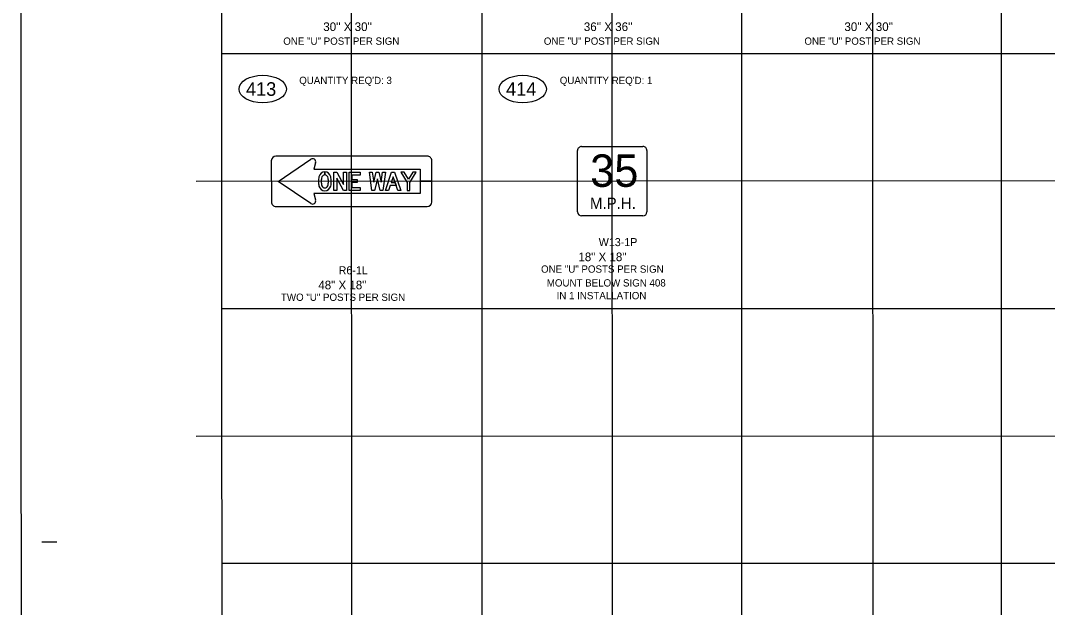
# Model space of a CAD drawing. Extents: x 1977705 to 1981198, y 827296 to 829291.
# Drawn here: x 1979337 to 1980184, y 827837 to 828321 of the extents above; entities that cross this region are included whole.
import ezdxf

# ---------------------------------------------------------------- set-up
doc = ezdxf.new("R2010")
doc.units = 0
for name, color, linetype in [('Level 3', 7, 'Continuous'), ('Level 34', 7, 'Continuous'), ('Level 43', 7, 'Continuous'), ('Level 46', 7, 'Continuous'), ('Level 5', 7, 'Continuous'), ('Level 7', 7, 'Continuous')]:
    doc.layers.add(name, color=color, linetype=linetype)

msp = doc.modelspace()

# ---------------------------------------------------------------- linework, layer by layer
at = {"layer": 'Level 3'}
msp.add_lwpolyline([(1981020.16, 828736.58), (1979336.66, 828735.68), (1979337.25, 827640.68), (1981020.75, 827641.58)], close=True, dxfattribs=at)
at = {"layer": 'Level 34'}
for p, q in [((1979610.04, 827663.85), (1979609.44, 828783.03)), ((1979824.92, 827663.96), (1979824.32, 828783.14)), ((1980039.8, 827664.08), (1980039.2, 828783.26)), ((1981002.08, 828188.92), (1979481.44, 828188.11)), ((1981002.19, 827978.73), (1979481.55, 827977.92))]:
    msp.add_line(p, q, dxfattribs=at)
at = {"layer": 'Level 43'}
for p, q in [((1979543.48, 828205.15), (1979543.5, 828171.13)), ((1979672, 828209), (1979547.26, 828208.93)), ((1979587.61, 828193.48), (1979587.61, 828195.91)), ((1979587.61, 828195.91), (1979587.61, 828193.48)), ((1979587.61, 828193.48), (1979587.61, 828195.91)), ((1979587.61, 828195.91), (1979587.61, 828193.48)), ((1979587.61, 828193.48), (1979587.61, 828193.48)), ((1979587.61, 828193.48), (1979587.61, 828193.48)), ((1979547.28, 828167.35), (1979672.02, 828167.42))]:
    msp.add_line(p, q, dxfattribs=at)
for points in [[(1979576.06, 828169.94), (1979549.16, 828188.14), (1979576.04, 828206.37)], [(1979580, 828203.51), (1979578.45, 828198.08), (1979666.34, 828198.13), (1979666.34, 828188.21), (1979675.79, 828188.22), (1979675.78, 828205.22)], [(1979675.8, 828171.21), (1979675.79, 828188.21), (1979666.34, 828188.21), (1979666.35, 828178.29), (1979578.46, 828178.24), (1979580.01, 828172.81)]]:
    msp.add_lwpolyline(points, dxfattribs=at)
for points in [[(1979595.15, 828180.61), (1979595.15, 828195.73), (1979597.56, 828195.73), (1979602.98, 828185.67), (1979602.97, 828195.73), (1979605.35, 828195.73), (1979605.36, 828180.61), (1979602.98, 828180.61), (1979597.53, 828190.73), (1979597.54, 828180.61)], [(1979595.15, 828180.61), (1979595.15, 828195.73), (1979597.56, 828195.73), (1979602.98, 828185.67), (1979602.97, 828195.73), (1979605.35, 828195.73), (1979605.36, 828180.61), (1979602.98, 828180.61), (1979597.53, 828190.73), (1979597.54, 828180.61)], [(1979595.15, 828180.61), (1979595.15, 828195.73), (1979597.56, 828195.73), (1979602.98, 828185.67), (1979602.97, 828195.73), (1979605.35, 828195.73), (1979605.36, 828180.61), (1979602.98, 828180.61), (1979597.53, 828190.73), (1979597.54, 828180.61)], [(1979616.79, 828193.32), (1979609.94, 828193.32), (1979609.94, 828189.69), (1979614.27, 828189.69), (1979614.27, 828187.27), (1979609.94, 828187.27), (1979609.95, 828183.03), (1979616.8, 828183.04), (1979616.8, 828180.62), (1979607.56, 828180.61), (1979607.55, 828195.73), (1979616.79, 828195.74)], [(1979616.79, 828193.32), (1979609.94, 828193.32), (1979609.94, 828189.69), (1979614.27, 828189.69), (1979614.27, 828187.27), (1979609.94, 828187.27), (1979609.95, 828183.03), (1979616.8, 828183.04), (1979616.8, 828180.62), (1979607.56, 828180.61), (1979607.55, 828195.73), (1979616.79, 828195.74)], [(1979616.79, 828193.32), (1979609.94, 828193.32), (1979609.94, 828189.69), (1979614.27, 828189.69), (1979614.27, 828187.27), (1979609.94, 828187.27), (1979609.95, 828183.03), (1979616.8, 828183.04), (1979616.8, 828180.62), (1979607.56, 828180.61), (1979607.55, 828195.73), (1979616.79, 828195.74)], [(1979627.89, 828187.57), (1979629.85, 828195.75), (1979632.09, 828195.75), (1979634.07, 828187.57), (1979635.19, 828195.75), (1979637.6, 828195.75), (1979635.52, 828180.63), (1979633.29, 828180.63), (1979630.97, 828190.22), (1979628.67, 828180.63), (1979626.44, 828180.63), (1979624.34, 828195.74), (1979626.75, 828195.74)], [(1979627.89, 828187.57), (1979629.85, 828195.75), (1979632.09, 828195.75), (1979634.07, 828187.57), (1979635.19, 828195.75), (1979637.6, 828195.75), (1979635.52, 828180.63), (1979633.29, 828180.63), (1979630.97, 828190.22), (1979628.67, 828180.63), (1979626.44, 828180.63), (1979624.34, 828195.74), (1979626.75, 828195.74)], [(1979627.89, 828187.57), (1979629.85, 828195.75), (1979632.09, 828195.75), (1979634.07, 828187.57), (1979635.19, 828195.75), (1979637.6, 828195.75), (1979635.52, 828180.63), (1979633.29, 828180.63), (1979630.97, 828190.22), (1979628.67, 828180.63), (1979626.44, 828180.63), (1979624.34, 828195.74), (1979626.75, 828195.74)], [(1979641.52, 828184.79), (1979640.12, 828180.64), (1979637.61, 828180.63), (1979642.66, 828195.75), (1979645.19, 828195.75), (1979650.27, 828180.64), (1979647.75, 828180.64), (1979646.35, 828184.79)], [(1979637.61, 828180.63), (1979642.66, 828195.75), (1979645.19, 828195.75), (1979650.27, 828180.64), (1979647.75, 828180.64), (1979643.93, 828192.02), (1979642.32, 828187.21), (1979645.54, 828187.21), (1979646.35, 828184.79), (1979641.52, 828184.79), (1979640.12, 828180.64)], [(1979637.61, 828180.63), (1979642.66, 828195.75), (1979645.19, 828195.75), (1979650.27, 828180.64), (1979647.75, 828180.64), (1979643.93, 828192.02), (1979642.32, 828187.21), (1979645.54, 828187.21), (1979646.35, 828184.79), (1979641.52, 828184.79), (1979640.12, 828180.64)], [(1979650.26, 828195.76), (1979655.44, 828187.26), (1979655.45, 828180.64), (1979657.83, 828180.65), (1979657.82, 828187.26), (1979662.99, 828195.76), (1979660.19, 828195.76), (1979656.63, 828189.9), (1979653.06, 828195.76)], [(1979650.26, 828195.76), (1979655.44, 828187.26), (1979655.45, 828180.64), (1979657.83, 828180.65), (1979657.82, 828187.26), (1979662.99, 828195.76), (1979660.19, 828195.76), (1979656.63, 828189.9), (1979653.06, 828195.76)], [(1979650.26, 828195.76), (1979655.44, 828187.26), (1979655.45, 828180.64), (1979657.83, 828180.65), (1979657.82, 828187.26), (1979662.99, 828195.76), (1979660.19, 828195.76), (1979656.63, 828189.9), (1979653.06, 828195.76)], [(1979642.32, 828187.21), (1979645.54, 828187.21), (1979643.93, 828192.02)]]:
    msp.add_lwpolyline(points, close=True, dxfattribs=at)
for centre, radius, start, end in [((1979547.26, 828205.15), 3.78, 90.03168, 180.03081), ((1979577.5, 828204.22), 2.6, 344.07596, 124.148), ((1979672, 828205.22), 3.78, 0.03081, 90.03168), ((1979547.28, 828171.13), 3.78, 180.03081, 270.03168), ((1979577.52, 828172.09), 2.6, 235.91363, 15.98567), ((1979672.02, 828171.2), 3.78, 270.03168, 0.03081)]:
    msp.add_arc(centre, radius, start, end, dxfattribs=at)
for centre, major_axis, start_param, end_param in [((1979587.64, 828190.8), (0, 5.12), 0.007008, 1.34227), ((1979587.64, 828190.8), (0, 5.12), 0.007008, 1.34227), ((1979587.64, 828190.8), (0, 5.12), 0.007008, 1.34227), ((1979587.57, 828190.8), (0, 5.12), 4.940915, 6.276178), ((1979587.57, 828190.8), (0, 5.12), 4.940915, 6.27603), ((1979587.57, 828190.8), (0, 5.12), 4.940915, 6.27603), ((1979597.57, 828188.22), (-0.01, 15.52), 1.327472, 1.575821), ((1979597.57, 828188.22), (-0.01, 15.52), 1.327472, 1.575821), ((1979597.57, 828188.22), (-0.01, 15.52), 1.327472, 1.575821), ((1979597.57, 828188.07), (-0.01, 15.52), 1.565772, 1.814121), ((1979597.57, 828188.07), (-0.01, 15.52), 1.565772, 1.814121), ((1979597.57, 828188.07), (-0.01, 15.52), 1.565772, 1.814121), ((1979595.9, 828188.42), (-0.01, 11.38), 1.267043, 1.594924), ((1979595.9, 828188.42), (-0.01, 11.38), 1.267042, 1.594924), ((1979595.9, 828188.42), (-0.01, 11.38), 1.267042, 1.594924), ((1979595.9, 828187.87), (-0.01, 11.38), 1.546668, 1.87455), ((1979595.9, 828187.87), (-0.01, 11.38), 1.546668, 1.87455), ((1979595.9, 828187.87), (-0.01, 11.38), 1.546668, 1.87455), ((1979587.53, 828190.95), (0, 2.53), 6.252339, 7.504367), ((1979587.53, 828190.95), (0, 2.53), 6.252339, 7.504367), ((1979587.53, 828190.95), (0, 2.53), 6.252339, 7.504367), ((1979587.69, 828190.95), (0, 2.53), 5.062003, 6.314032), ((1979587.69, 828190.95), (0, 2.53), 5.062003, 6.313732), ((1979587.69, 828190.95), (0, 2.53), 5.062003, 6.313732), ((1979579.33, 828188.41), (-0.01, 11.38), 4.688261, 5.016143), ((1979579.33, 828188.41), (-0.01, 11.38), 4.688261, 5.016143), ((1979579.33, 828188.41), (-0.01, 11.38), 4.688261, 5.016143), ((1979579.33, 828187.86), (-0.01, 11.38), 4.408635, 4.736517), ((1979579.33, 828187.86), (-0.01, 11.38), 4.408635, 4.736517), ((1979579.33, 828187.86), (-0.01, 11.38), 4.408635, 4.736517), ((1979577.65, 828188.21), (-0.01, 15.52), 4.707364, 4.955713), ((1979577.65, 828188.21), (-0.01, 15.52), 4.707364, 4.955713), ((1979577.65, 828188.21), (-0.01, 15.52), 4.707364, 4.955713), ((1979577.65, 828188.06), (-0.01, 15.52), 4.469065, 4.717414), ((1979577.65, 828188.06), (-0.01, 15.52), 4.469065, 4.717414), ((1979577.65, 828188.06), (-0.01, 15.52), 4.469065, 4.717414), ((1979587.65, 828185.48), (0, 5.12), 1.799323, 3.134585), ((1979587.65, 828185.48), (0, 5.12), 1.799323, 3.134585), ((1979587.65, 828185.48), (0, 5.12), 1.799323, 3.134585), ((1979587.54, 828185.32), (0, 2.53), 1.920411, 3.172439), ((1979587.54, 828185.32), (0, 2.53), 1.920411, 3.172439), ((1979587.54, 828185.32), (0, 2.53), 1.920411, 3.172439), ((1979587.69, 828185.32), (0, 2.53), 3.110746, 4.362774), ((1979587.69, 828185.32), (0, 2.53), 3.110746, 4.362775), ((1979587.69, 828185.32), (0, 2.53), 3.110746, 4.362775), ((1979587.58, 828185.48), (0, 5.12), 3.1486, 4.483863), ((1979587.58, 828185.48), (0, 5.12), 3.1486, 4.483863), ((1979587.58, 828185.48), (0, 5.12), 3.1486, 4.483863)]:
    msp.add_ellipse(centre, major_axis=major_axis, ratio=0.985, start_param=start_param, end_param=end_param, dxfattribs=at)
at = {"layer": 'Level 46'}
msp.add_line((1979853.23, 828213.58), (1979853.26, 828163.03), dxfattribs=at)
for points in [[(1979796.04, 828163), (1979796.01, 828213.55)], [(1979799.35, 828216.89), (1979824.62, 828216.9)], [(1979824.62, 828216.9), (1979849.89, 828216.92)], [(1979824.65, 828159.68), (1979799.38, 828159.67)], [(1979849.92, 828159.69), (1979824.65, 828159.68)]]:
    msp.add_lwpolyline(points, dxfattribs=at)
for centre, start, end in [((1979799.35, 828213.55), 90.01778, 180.03081), ((1979849.9, 828213.58), 0.03081, 90.03081), ((1979799.38, 828163.01), 180.03081, 270.03081), ((1979849.92, 828163.03), 270.03081, 0.03081)]:
    msp.add_arc(centre, 3.34, start, end, dxfattribs=at)
at = {"layer": 'Level 5'}
msp.add_line((1979354.1, 827891.16), (1979366.6, 827891.17), dxfattribs=at)
at = {"layer": 'Level 7'}
msp.add_lwpolyline([(1981001.8, 828714.37), (1979502.12, 828713.56), (1979502.69, 827663.79), (1981002.36, 827664.6)], close=True, dxfattribs=at)
for points in [[(1979716.94, 828713.68), (1979716.94, 827663.9)], [(1979931.19, 828713.79), (1979931.19, 827664.02)], [(1980145.44, 828713.91), (1980145.44, 827664.13)], [(1979502.35, 828293.56), (1981002.02, 828293.56)], [(1979502.46, 828083.56), (1981002.14, 828083.56)], [(1979502.58, 827873.56), (1981002.25, 827873.56)]]:
    msp.add_lwpolyline(points, dxfattribs=at)
for centre in [(1979536.36, 828264.23), (1979750.83, 828264.23)]:
    msp.add_ellipse(centre, major_axis=(-19.54, 0), ratio=0.580127, dxfattribs=at)

# ---------------------------------------------------------------- texts
at = {"layer": 'Level 46'}
for s, height, p in [('35', 26.703, (1979806.45, 828183.64)), ('M.P.H.', 9.27, (1979806.23, 828165.47))]:
    msp.add_text(s, height=height, rotation=0.03081, dxfattribs=at).set_placement(p)
at = {"layer": 'Level 7'}
for s, height, p in [("30'' X 30''", 7.125, (1979586.32, 828312)), ("36'' X 36''", 7.125, (1979801.2, 828312)), ("30'' X 30''", 7.125, (1980016.08, 828312.02)), ('ONE "U" POST PER SIGN', 6, (1979553.32, 828300.69)), ('ONE "U" POST PER SIGN', 6, (1979768.2, 828300.69)), ('ONE "U" POST PER SIGN', 6, (1979983.08, 828300.69)), ("QUANTITY REQ'D: 3", 6, (1979566.48, 828268.36)), ("QUANTITY REQ'D: 1", 6, (1979781.35, 828268.36)), ('W13-1P', 6.6, (1979813.47, 828134.81)), ('18" X 18"', 7.125, (1979796.7, 828122.41)), ('R6-1L', 6.6, (1979598.99, 828111.61)), ('ONE "U" POSTS PER SIGN', 6, (1979765.89, 828112.92)), ('48" X 18"', 7.125, (1979582.23, 828099.21)), ('MOUNT BELOW SIGN 408 ', 6, (1979770.65, 828101.54)), ('TWO "U" POSTS PER SIGN', 6, (1979551.42, 828089.72)), ('IN 1 INSTALLATION', 6, (1979778.75, 828091.04))]:
    msp.add_text(s, height=height, dxfattribs=at).set_placement(p)
for s, p in [('413', (1979522.56, 828258.63)), ('414', (1979737.02, 828258.63))]:
    msp.add_text(s, height=11.202, rotation=359.99624, dxfattribs=at).set_placement(p)

doc.saveas('drawing.dxf')
